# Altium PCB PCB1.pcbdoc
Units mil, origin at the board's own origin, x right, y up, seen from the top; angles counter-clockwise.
Board outline 3256.89 x 1440 mil, 2 copper layers (Top Layer, Bottom Layer); 13 components, 17 nets, 89 pads, 27 vias.
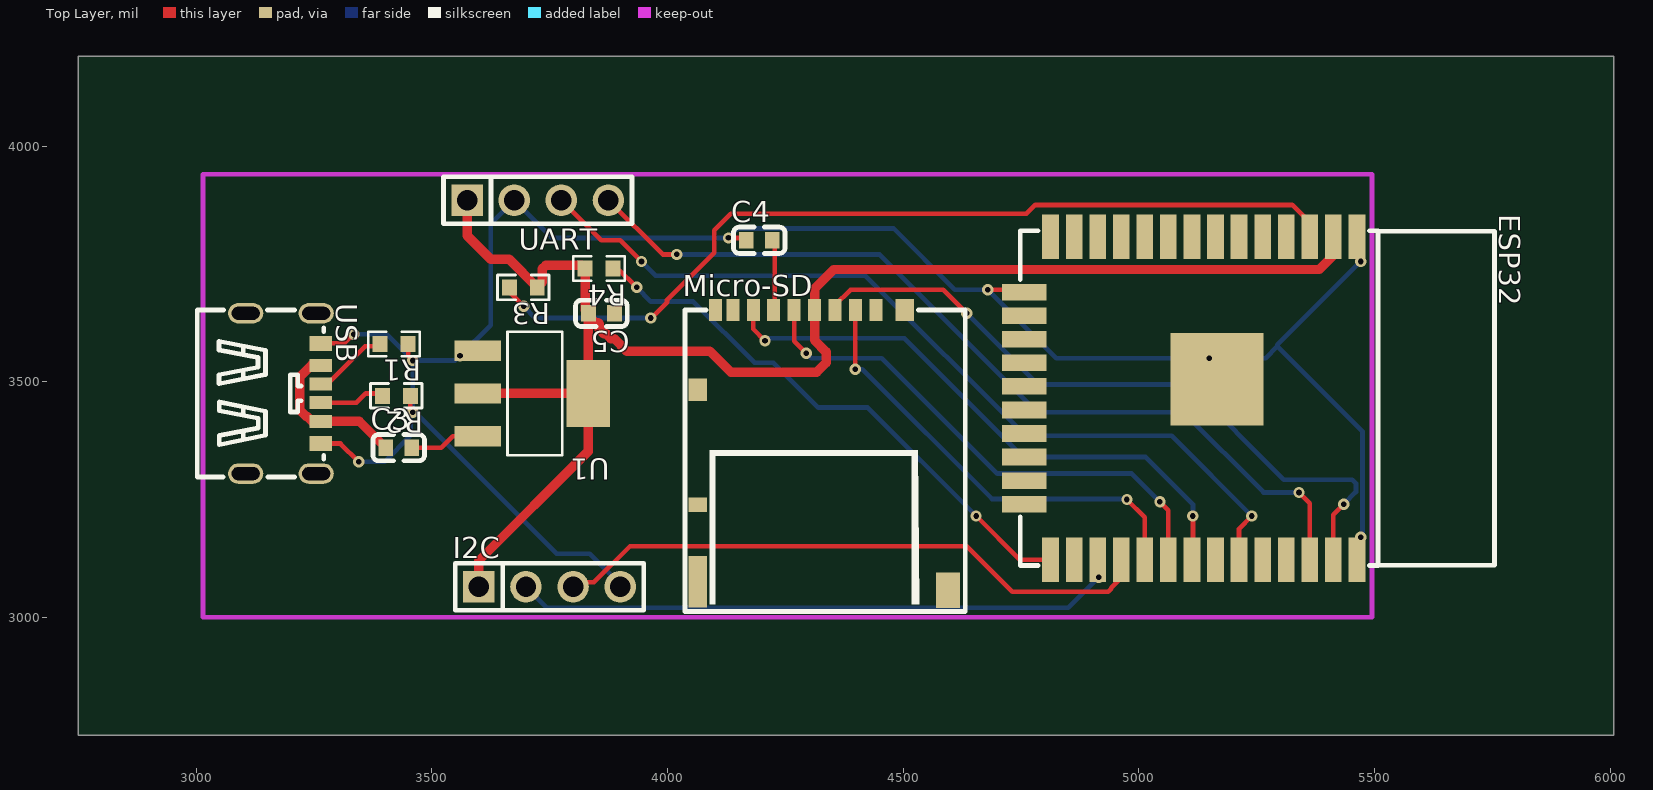
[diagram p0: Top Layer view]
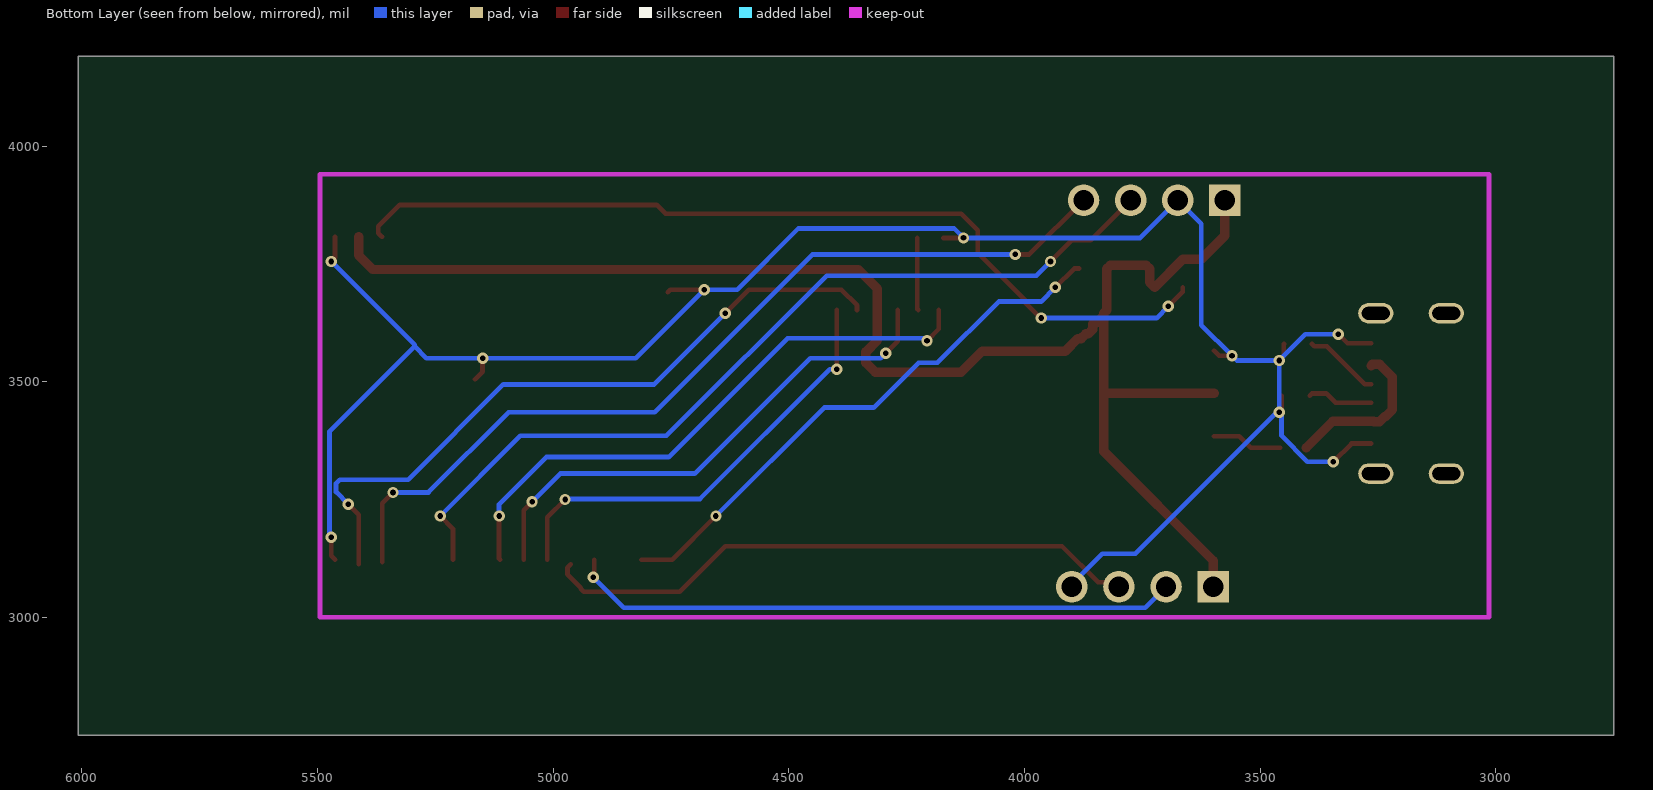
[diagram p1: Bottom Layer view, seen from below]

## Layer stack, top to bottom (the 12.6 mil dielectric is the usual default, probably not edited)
Top Layer: signal copper (thickness not stored)
Dielectric: dielectric 12.6, FR-4, Dk 4.8
Bottom Layer: signal copper (thickness not stored)

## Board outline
6006.89,2750 2750,2750 2750,4190 6006.89,4190

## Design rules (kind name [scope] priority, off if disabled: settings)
BoardOutlineClearance copperThickness1oz [All] p0: genericclearance=10 ignorepadtopadclearanceinfootprint=FALSE except(0: Arc-SplitContinuation Track-SplitContinuation SMDPad-SplitContinuation THPad-SplitContinuation Via-SplitContinuation Fill-SplitContinuation Poly-SplitContinuation Region-SplitContinuation Text-SplitContinuation; 6: Track-CutoutEdge SMDPad-CutoutEdge THPad-CutoutEdge Via-CutoutEdge Region-CutoutEdge; 11.8: Track-OutlineEdge SMDPad-OutlineEdge THPad-OutlineEdge Via-OutlineEdge Fill-OutlineEdge Region-OutlineEdge Poly-OutlineEdge Text-OutlineEdge Fill-CutoutEdge)
BoardOutlineClearance copperThickness2oz [All] p0: genericclearance=10 ignorepadtopadclearanceinfootprint=FALSE except(0: Arc-SplitContinuation Track-SplitContinuation SMDPad-SplitContinuation THPad-SplitContinuation Via-SplitContinuation Fill-SplitContinuation Poly-SplitContinuation Region-SplitContinuation Text-SplitContinuation; 6: Track-CutoutEdge SMDPad-CutoutEdge THPad-CutoutEdge Via-CutoutEdge Region-CutoutEdge; 11.8: Track-OutlineEdge SMDPad-OutlineEdge THPad-OutlineEdge Via-OutlineEdge Fill-OutlineEdge Region-OutlineEdge Poly-OutlineEdge Text-OutlineEdge Fill-CutoutEdge)
Clearance copperThickness1oz [(InNet('+5V') OR InNet('$1N1636') OR InNet('GND') OR InNet('+3.3V') OR InNet('IO19') OR InNet('IO18') OR InNet('IO23') OR InNet('IO5') OR InNet('$1N1353') OR InNet('$1N1481') OR InNet('IO16') OR InNet('IO17') OR InNet('IO21') OR InNet('IO22') OR InNet('$1N1044') OR InNet('$1N1054') OR InNet('$1N1058'))] p1: gap=7 ignorepadtopadclearanceinfootprint=FALSE except(4: Track-Track; 6: Track-SMDPad SMDPad-SMDPad Track-THPad SMDPad-THPad THPad-THPad Track-Via SMDPad-Via THPad-Via Via-Via SMDPad-Fill THPad-Fill Via-Fill Fill-Fill Track-Region SMDPad-Region THPad-Region Via-Region Region-Region Track-Poly SMDPad-Poly THPad-Poly Via-Poly Fill-Poly Region-Poly Poly-Poly Track-Text SMDPad-Text THPad-Text Via-Text Fill-Text Region-Text Poly-Text Text-Text; 6.9: Track-Hole SMDPad-Hole THPad-Hole Via-Hole Fill-Hole Region-Hole Poly-Hole Text-Hole Sheet-Hole; 11.8: Track-Fill Fill-Region Track-Sheet SMDPad-Sheet THPad-Sheet Via-Sheet Fill-Sheet Region-Sheet Poly-Sheet Text-Sheet)
Clearance copperThickness2oz [All] p1: gap=7 ignorepadtopadclearanceinfootprint=FALSE except(6: Track-SMDPad SMDPad-SMDPad Track-THPad SMDPad-THPad THPad-THPad Track-Via SMDPad-Via THPad-Via Via-Via SMDPad-Fill THPad-Fill Via-Fill Fill-Fill Track-Region SMDPad-Region THPad-Region Via-Region Region-Region Track-Poly SMDPad-Poly THPad-Poly Via-Poly Fill-Poly Region-Poly Poly-Poly Track-Text SMDPad-Text THPad-Text Via-Text Fill-Text Region-Text Poly-Text Text-Text; 6.9: Track-Hole SMDPad-Hole THPad-Hole Via-Hole Fill-Hole Region-Hole Poly-Hole Text-Hole Sheet-Hole; 8: Track-Track; 11.8: Track-Fill Fill-Region Track-Sheet SMDPad-Sheet THPad-Sheet Via-Sheet Fill-Sheet Region-Sheet Poly-Sheet Text-Sheet)
DiffPairsRouting differentialPair [All] p1: maxuncoupledlength=10 minlimit=6 maxlimit=6 mostfreqgap=6 toplayer_minwidth=5 toplayer_prefwidth=10 toplayer_maxwidth=100 bottomlayer_minwidth=5 bottomlayer_prefwidth=10 bottomlayer_maxwidth=100
PasteMaskExpansion pasteMaskExpansion [All] p1: expansion=0
PlaneConnect innerPlane [All] p1: planeconnectstyle=Relief reliefexpansion=20 reliefentries=4 reliefconductorwidth=10 reliefairgap=10
PolygonConnect copperRegion [All] p1: connectstyle=Relief reliefentries=4 reliefconductorwidth=10 polygonreliefangle="90 Angle" airgapwidth=10
RoutingVias viaSize [All] p1: viastyle="Through Hole" holewidth=12.0078 minholewidth=11.811 maxholewidth=248.0314 width=24.0158 minwidth=19.685 maxwidth=393.7008
SolderMaskExpansion solderMaskExpansion [All] p1: useseparateexpansions=TRUE expansion=2 expansionbottom=2
Width copperThickness1oz [All] p1: maxlimit=100 minlimit=5 preferedwidth=10
Width copperThickness2oz [All] p1: maxlimit=100 minlimit=8 preferedwidth=10

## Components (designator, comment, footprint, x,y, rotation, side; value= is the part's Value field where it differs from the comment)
C3 "CC0603KRX7R9BB104" C0603 3429.45,3360 r0 top
C4 "CC0603KRX7R9BB104" C0603 4194.45,3800 r0 top
C5 "CC0603KRX7R9BB104" C0603 3859.45,3645 r180 top
ESP32 "ESP32-WROOM-32" WIFIM-SMD_39P-L25.5-W18.0-P1.27 5109.45,3465 r270 top
I2C "HX PZ2.54-1x4P ZZ" HDR-TH_4P-P2.54-V-M 3749.45,3065 r0 top
Micro-SD "DM3AT-SF-PEJM5" SD-SMD_DM3AT-SF-PEJM5 4329.45,3355 r0 top
R1 "0603WAF5101T5E" R0603 3419.45,3580 r180 top
R2 "0603WAF5101T5E" R0603 3424.45,3470 r180 top
R3 "0603WAF5101T5E" R0603 3693.77,3700 r180 top
R4 "0603WAF5101T5E" R0603 3854.45,3740 r180 top
U1 "AMS1117-3.3_C6186" SOT-223-3_L6.5-W3.4-P2.30-LS7.0-BR 3714.45,3475 r180 top
UART "HX PZ2.54-1x4P ZZ" HDR-TH_4P-P2.54-V-M 3724.45,3885 r0 top
USB "USB-TYPE-C-009" TYPE-C-SMD_TYPE-C-6P 3184.45,3475 r270 top

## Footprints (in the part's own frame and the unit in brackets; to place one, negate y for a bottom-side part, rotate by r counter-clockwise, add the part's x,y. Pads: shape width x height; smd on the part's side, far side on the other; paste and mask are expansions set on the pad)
C0603 [mm]
  rect 0.8x0.9 smd: 1(-0.7,0) 2(0.7,0)
  silkscreen extent -1.39,-0.71 1.39,0.71
HDR-TH_4P-P2.54-V-M [mm]
  rect 1.7x1.7 hole 1.1: 1(-3.81,0)
  round 1.7 hole 1.1: 2(-1.27,0) 3(1.27,0) 4(3.81,0)
  silkscreen extent -5.08,-1.27 5.08,1.27
R0603 [mil]
  rect 31.75x34.02 smd: 1(-29.66,0) 2(29.66,0)
  silkscreen extent -55,-26 55,26
SD-SMD_DM3AT-SF-PEJM5 [mm]
  rect 0.7x1.2 smd: 1(2.85,7.55) 2(1.75,7.55) 3(0.65,7.55) 4(-0.45,7.55) 5(-1.55,7.55) 6(-2.65,7.55) 7(-3.75,7.55) 8(-4.85,7.55) 9(-5.8,7.55)
  rect 1x1.2 smd: 10(-6.75,3.25) 14(4.4,7.55)
  rect 1x0.8 smd: 11(-6.75,-2.95)
  rect 1x2.8 smd: 12(-6.75,-7.1)
  rect 1.3x1.9 smd: 13(6.75,-7.55)
  silkscreen extent -7.44,-8.71 7.68,7.55
SOT-223-3_L6.5-W3.4-P2.30-LS7.0-BR [mm]
  rect 2.5x1.1 smd: 1(2.97,-2.3) 2(2.97,0) 3(2.97,2.3)
  rect 2.34x3.6 smd: 4(-2.97,0)
  silkscreen extent -1.57,-3.33 1.37,3.33
TYPE-C-SMD_TYPE-C-6P [mm]
  oval 1.1x1.9 hole 0.7 slot 1.5 at 90 deg: 7(-4.32,1.775) 7(-4.32,-2.025) 7(4.32,1.775) 7(4.32,-2.025)
  rect 0.7x1.2 smd: A5(-0.5,2.025) A9(1.5,2.025) B5(0.5,2.025) B9(-1.5,2.025)
  rect 0.8x1.2 smd: A12(2.7,2.025) B12(-2.7,2.025)
  silkscreen extent -4.5,-4.63 4.5,2.18
WIFIM-SMD_39P-L25.5-W18.0-P1.27 [mm]
  rect 2.4x0.9 smd: 1(-8.7,8.965) 2(-8.7,7.695) 3(-8.7,6.425) 4(-8.7,5.155) 5(-8.7,3.885) 6(-8.7,2.615) 7(-8.7,1.345) 8(-8.7,0.075) 9(-8.7,-1.195) 10(-8.7,-2.465) 11(-8.7,-3.735) 12(-8.7,-5.005) 13(-8.7,-6.275) 14(-8.7,-7.545) 25(8.7,-7.545) 26(8.7,-6.275) 27(8.7,-5.005) 28(8.7,-3.735) 29(8.7,-2.465) 30(8.7,-1.195) 31(8.7,0.075) 32(8.7,1.345) 33(8.7,2.615) 34(8.7,3.885) 35(8.7,5.155) 36(8.7,6.425) 37(8.7,7.695) 38(8.7,8.965)
  rect 0.9x2.4 smd: 15(-5.715,-8.965) 16(-4.445,-8.965) 17(-3.175,-8.965) 18(-1.905,-8.965) 19(-0.635,-8.965) 20(0.635,-8.965) 21(1.905,-8.965) 22(3.175,-8.965) 23(4.445,-8.965) 24(5.715,-8.965)
  rect 5x5 smd: 39(-1.017,1.422)
  silkscreen extent -9.02,-9.17 9.02,16.39

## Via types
v1: diameter 24.02, hole 12.01, Top Layer to Bottom Layer, 27 vias

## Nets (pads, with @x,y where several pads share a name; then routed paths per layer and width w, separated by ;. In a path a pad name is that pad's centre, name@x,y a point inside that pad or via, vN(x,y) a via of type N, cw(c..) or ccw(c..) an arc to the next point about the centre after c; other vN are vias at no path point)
$1N1044: R1.2 USB.A5 | length 161
  Top Layer w10: USB.A5 3277.74,3494.68 3358.05,3575 3384.79,3575 R1.2
$1N1054: R2.2 USB.B5 | length 140.8
  Top Layer w10: USB.B5 3339.76,3455.32 3359.45,3475 3389.79,3475 R2.2
$1N1058: C3.2 U1.3 | length 150.6
  Top Layer w10: C3.2 3519.45,3360 3543.9,3384.45 U1.3
$1N1353: ESP32.3 R3.2 | length 1914
  Top Layer w10: R3.2 3664.11,3690.34 v1(3694.45,3660) ; v1(3964.45,3635) 3965.04,3635 3998.74,3668.7 3998.74,3673.7 4098.74,3773.7 4098.74,3820.79 4134.17,3856.22 4761.2,3856.22 4779.99,3875 5325.41,3875 5370.88,3829.53 5370.88,3815.39 5363,3807.51 ESP32.3
  Bottom Layer w10: v1(3694.45,3660) 3719.45,3635 v1(3964.45,3635)
$1N1481: ESP32.25 R4.1 | length 1184.1
  Top Layer w10: R4.1 3894.45,3740 v1(3934.45,3700) ; v1(4654.45,3215) 4746.96,3122.49 ESP32.25
  Bottom Layer w10: v1(3934.45,3700) 3964.45,3670 4054.45,3670 4184.45,3540 4224.45,3540 4319.45,3445 4424.45,3445 v1(4654.45,3215)
$1N1636: C4.2 Micro-SD.6 | length 153.5
  Top Layer w10: Micro-SD.6 4227.01,3654.14 C4.2@4227.01,3805
+3.3V: C5.2 ESP32.2 I2C.1 Micro-SD.4 R3.1 R4.2 U1.2 U1.4 UART.1 | length 3324.6
  Top Layer w20: UART.1 3574.45,3810 3624.45,3760 3663.43,3760 R3.1 3734.45,3711.02 3734.45,3740 3741.52,3747.07 3817.71,3747.07 R4.2 3824.79,3652.1 C5.2 C5.2@3831.89,3640 ; U1.2 U1.4 ; I2C.1 3599.45,3120 3831.37,3351.93 U1.4 ; ESP32.2 5412.4,3767.96 5382.44,3737.99 4352.44,3737.99 4311.73,3697.28 Micro-SD.4 4311.73,3587.72 4336.16,3563.28 4336.16,3540 4316.16,3520 4134.45,3520 4089.45,3565 3913.01,3565 3886.71,3591.3 3879.64,3591.3 3869.64,3601.3 3864.64,3601.3 3855.27,3610.66 3855.27,3622.73 3853.01,3625 3846.89,3625 C5.2@3831.89,3640 ; U1.4 3831.89,3475.51 C5.2@3831.89,3640
+5V: C3.1 USB.A9 USB.B9 | length 343.1
  Top Layer w20: USB.B9 3261.69,3536.53 3246.01,3536.53 3219.45,3509.97 3219.45,3440.03 3233.93,3425.55 3236,3425.55 3246.55,3415 3258.23,3415 3259.17,3415.95 USB.A9 3345.94,3415.95 C3.1
GND: C4.1 ESP32.1 ESP32.15 ESP32.38 ESP32.39 I2C.4 R1.1 R2.1 U1.1 UART.2 USB.A12 USB.B12 | length 4614.5
  Top Layer w10: USB.A12 3305.74,3368.7 v1(3344.45,3330) ; USB.B12 3314.45,3581.3 v1(3333.8,3600.65) ; R1.1 3449.45,3579.66 3449.45,3555 v1(3459.45,3545) ; R2.1 3454.11,3440.34 v1(3459.45,3435) ; v1(3559.45,3555) 3586.97,3555 U1.1 ; v1(4129.01,3805) C4.1@4171.89,3805 ; v1(4679.45,3695) 4751.49,3695 ESP32.15 ; v1(5149.45,3550) 5149.45,3521.03 ESP32.39 ; ESP32.38 5470.63,3130.71 v1(5470.63,3169.77) ; ESP32.1 5462.4,3763.22 v1(5470.63,3755)
  Bottom Layer w10: v1(3333.8,3600.65) 3403.8,3600.65 v1(3459.45,3545) ; v1(3344.45,3330) 3399.45,3330 3454.45,3385 3454.45,3430 v1(3459.45,3435) ; I2C.4 3899.45,3070 3834.45,3135 3764.45,3135 3464.45,3435 v1(3459.45,3435) ; v1(5470.63,3169.77) 5474.45,3173.59 5474.45,3394.1 5293.54,3575 ; v1(5470.63,3755) 5293.54,3577.92 5293.54,3575 ; v1(3459.45,3435) v1(3459.45,3545) ; v1(3459.45,3545) 3549.45,3545 v1(3559.45,3555) 3624.45,3620 3624.45,3835 UART.2 3754.45,3805 v1(4129.01,3805) 4149.01,3825 4479.45,3825 4609.45,3695 v1(4679.45,3695) 4824.45,3550 v1(5149.45,3550) 5268.54,3550 5293.54,3575
IO5: ESP32.29 Micro-SD.2 | length 960
  Top Layer w10: v1(4398.2,3526.24) 4398.2,3652.11 Micro-SD.2 ; v1(4974.45,3250) 5012.4,3212.04 ESP32.29
  Bottom Layer w10: v1(4398.2,3526.24) 4413.2,3526.24 4688.38,3251.07 4973.38,3251.07 v1(4974.45,3250)
IO16: ESP32.27 I2C.2 | length 1298.4
  Top Layer w10: ESP32.27 4912.4,3087.04 v1(4914.45,3085)
  Bottom Layer w10: I2C.2 3743.89,3020.55 4850,3020.55 v1(4914.45,3085)
IO17: ESP32.28 I2C.3 | length 1286.4
  Top Layer w10: I2C.3 3808.79,3074.34 3843.59,3074.34 3920.17,3150.92 4634.88,3150.92 4731.45,3054.34 4790.05,3054.34 4790.14,3054.26 4934.67,3054.26 4941.1,3060.69 4941.1,3063.03 4969.41,3091.34 4969.41,3105.48 ESP32.28@4962.4,3112.49
IO18: ESP32.30 Micro-SD.5 | length 1113.5
  Top Layer w10: Micro-SD.5 4268.42,3586.03 v1(4294.45,3560) ; v1(5044.45,3245) 5062.4,3227.04 ESP32.30
  Bottom Layer w10: v1(4294.45,3560) 4304.45,3550 4454.45,3550 4699.45,3305 4984.45,3305 v1(5044.45,3245)
IO19: ESP32.31 Micro-SD.7 | length 1249.6
  Top Layer w10: Micro-SD.7 4181.81,3611.78 v1(4206.52,3587.07) ; ESP32.31 5114.45,3124.53 v1(5114.45,3215)
  Bottom Layer w10: v1(4206.52,3587.07) 4211.52,3592.07 4502.37,3592.07 4754.45,3340 5014.45,3340 5114.45,3240 v1(5114.45,3215)
IO21: ESP32.33 UART.3 | length 1846.2
  Top Layer w10: UART.3 3859.45,3800 3899.45,3800 v1(3944.45,3755) ; ESP32.33 5212.4,3187.96 v1(5239.45,3215)
  Bottom Layer w10: v1(3944.45,3755) 3974.45,3725 4419.45,3725 4759.45,3385 5069.45,3385 v1(5239.45,3215)
IO22: ESP32.36 UART.4 | length 1878.8
  Top Layer w10: UART.4 3989.45,3770 v1(4019.45,3770) ; v1(5339.45,3265) 5362.4,3242.04 ESP32.36@5362.4,3117.49
  Bottom Layer w10: v1(4019.45,3770) 4449.45,3770 4784.45,3435 5094.45,3435 5264.45,3265 v1(5339.45,3265)
IO23: ESP32.37 Micro-SD.3 | length 1490.4
  Top Layer w10: Micro-SD.3 4355.04,3661.88 4388.16,3695 4584.45,3695 v1(4634.45,3645) ; ESP32.37@5412.4,3112.49 5412.4,3217.96 v1(5434.45,3240)
  Bottom Layer w10: v1(4634.45,3645) 4785.3,3494.14 5105.3,3494.14 5307.37,3292.07 5452.37,3292.07 5460.43,3284.02 5460.43,3265.98 v1(5434.45,3240)
pads on no net: C5.1 ESP32.4 ESP32.5 ESP32.6 ESP32.7 ESP32.8 ESP32.9 ESP32.10 ESP32.11 ESP32.12 ESP32.13 ESP32.14 ESP32.16 ESP32.17 ESP32.18 ESP32.19 ESP32.20 ESP32.21 ESP32.22 ESP32.23 ESP32.24 ESP32.26 ESP32.32 ESP32.34 ESP32.35 Micro-SD.1 Micro-SD.8 Micro-SD.9 Micro-SD.10 Micro-SD.11 Micro-SD.12 Micro-SD.13 Micro-SD.14 USB.7

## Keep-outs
Board Outline Layer:
  lines w10: 3014.45,3000 5494.45,3000 5494.45,3940 3014.45,3940 3014.45,3000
